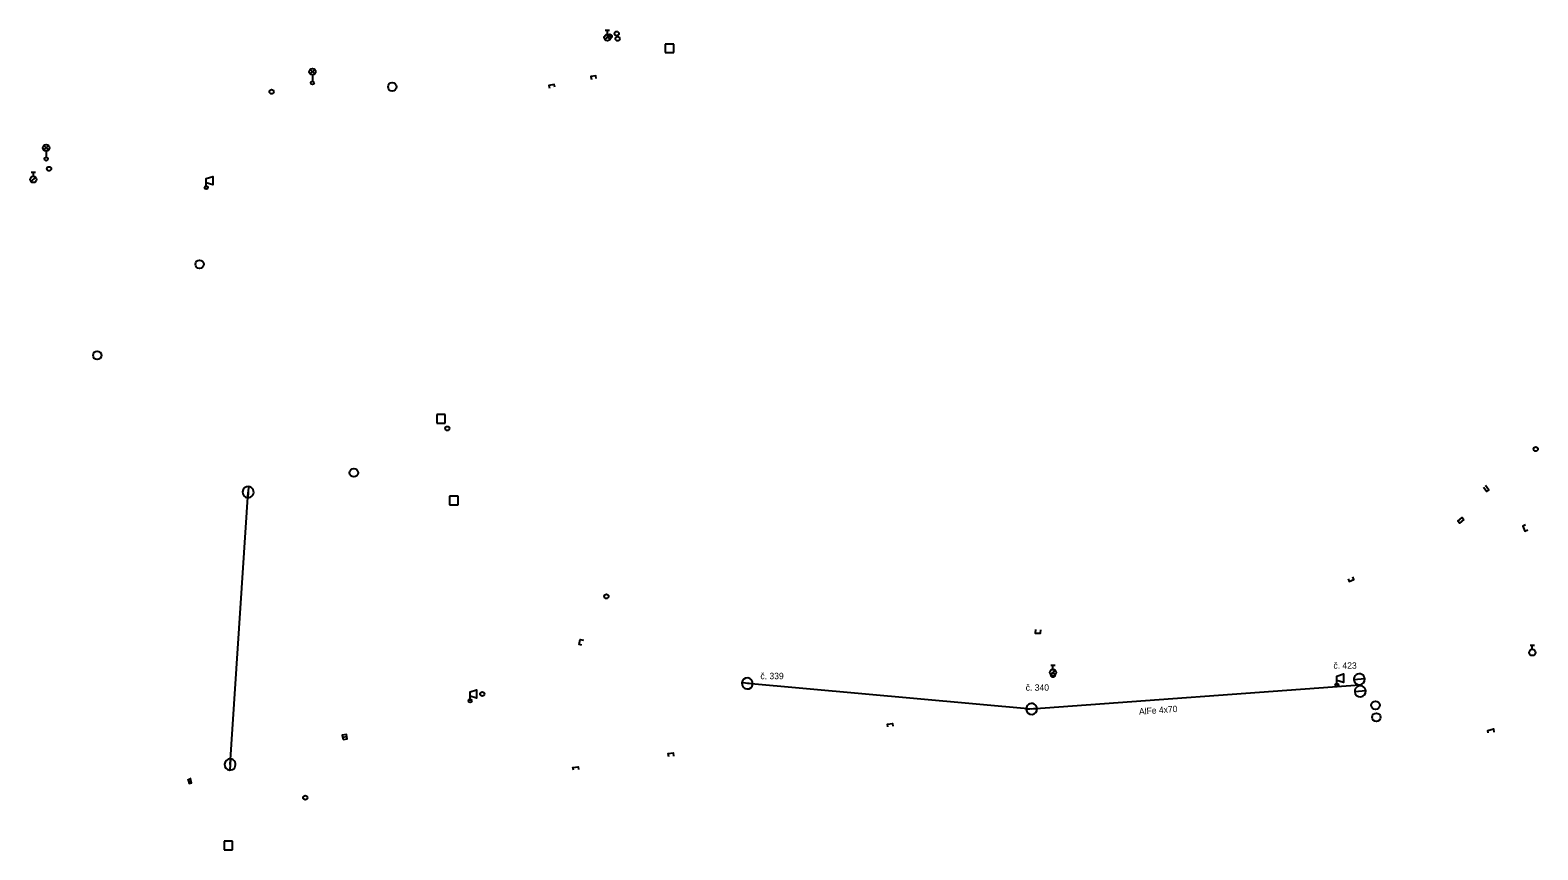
# Model space of a CAD drawing. Extents: x -577028 to -568584, y -1207664 to -1202947.
# Drawn here: x -575239.9 to -575063.1, y -1204378.5 to -1204282.4 of the extents above; entities that cross this region are included whole.
import ezdxf

# ---------------------------------------------------------------- set-up
doc = ezdxf.new("R2010")
doc.units = 0
for name, color, linetype in [('CIZÍ_NADZEM', 7, 'Continuous'), ('ELE_EON', 7, 'Continuous'), ('ELE_EON_POPIS', 7, 'Continuous')]:
    doc.layers.add(name, color=color, linetype=linetype)

msp = doc.modelspace()

# ---------------------------------------------------------------- linework, layer by layer
at = {"layer": 'CIZÍ_NADZEM'}
for p, q in [((-575172.48, -1204282.38), (-575171.98, -1204282.38)), ((-575172.23, -1204282.88), (-575172.23, -1204282.38)), ((-575172.52, -1204283.48), (-575171.93, -1204283.02)), ((-575164.44, -1204284.01), (-575165.44, -1204284.01)), ((-575165.44, -1204284.01), (-575165.44, -1204285.01)), ((-575164.44, -1204285.01), (-575164.44, -1204284.01)), ((-575165.44, -1204285.01), (-575164.44, -1204285.01)), ((-575207.08, -1204287.51), (-575206.56, -1204286.98)), ((-575206.55, -1204287.51), (-575207.08, -1204286.98)), ((-575206.82, -1204287.62), (-575206.82, -1204288.37)), ((-575238.31, -1204296.43), (-575237.79, -1204295.9)), ((-575237.78, -1204296.43), (-575238.31, -1204295.9)), ((-575238.05, -1204296.54), (-575238.05, -1204297.29)), ((-575239.84, -1204300.12), (-575239.25, -1204299.66)), ((-575239.8, -1204299.02), (-575239.3, -1204299.02)), ((-575239.55, -1204299.52), (-575239.55, -1204299.02)), ((-575191.24, -1204327.46), (-575192.24, -1204327.46)), ((-575192.24, -1204327.46), (-575192.24, -1204328.46)), ((-575192.24, -1204328.46), (-575191.24, -1204328.46)), ((-575191.24, -1204328.46), (-575191.24, -1204327.46)), ((-575189.73, -1204337.05), (-575190.73, -1204337.05)), ((-575190.73, -1204337.05), (-575190.73, -1204338.05)), ((-575189.73, -1204338.05), (-575189.73, -1204337.05)), ((-575190.73, -1204338.05), (-575189.73, -1204338.05)), ((-575064.02, -1204354.5), (-575063.52, -1204354.5)), ((-575063.77, -1204355), (-575063.77, -1204354.5)), ((-575120.27, -1204357.96), (-575119.68, -1204357.5)), ((-575120.23, -1204356.85), (-575119.73, -1204356.85)), ((-575119.98, -1204357.35), (-575119.98, -1204356.85)), ((-575203.28, -1204365.33), (-575202.78, -1204365.25)), ((-575216.19, -1204377.53), (-575217.19, -1204377.53)), ((-575217.19, -1204377.53), (-575217.19, -1204378.53)), ((-575216.19, -1204378.53), (-575216.19, -1204377.53)), ((-575217.19, -1204378.53), (-575216.19, -1204378.53))]:
    msp.add_line(p, q, dxfattribs=at)
for points in [[(-575173.53, -1204288.05), (-575173.6, -1204287.73), (-575174.18, -1204287.83), (-575174.11, -1204288.17)], [(-575178.41, -1204289.05), (-575178.48, -1204288.74), (-575179.11, -1204288.87), (-575179.04, -1204289.18)], [(-575219.27, -1204300.84), (-575219.27, -1204299.79), (-575218.52, -1204299.54), (-575218.52, -1204300.54), (-575219.27, -1204300.29)], [(-575069.49, -1204335.97), (-575069.11, -1204336.49), (-575068.86, -1204336.33), (-575069.24, -1204335.8)], [(-575071.81, -1204339.78), (-575072.29, -1204340.2), (-575072.49, -1204339.97), (-575072.01, -1204339.55), (-575071.81, -1204339.78)], [(-575064.57, -1204340.41), (-575064.89, -1204340.55), (-575064.65, -1204341.14), (-575064.31, -1204340.98)], [(-575085.38, -1204346.74), (-575085.25, -1204347.04), (-575084.69, -1204346.81), (-575084.82, -1204346.5)], [(-575122.04, -1204352.68), (-575122.06, -1204353.1), (-575121.44, -1204353.11), (-575121.42, -1204352.71)], [(-575175.24, -1204354.51), (-575175.55, -1204354.44), (-575175.42, -1204353.85), (-575175.03, -1204353.95)], [(-575086.68, -1204359.2), (-575086.68, -1204358.15), (-575085.93, -1204357.9), (-575085.93, -1204358.9), (-575086.68, -1204358.65)], [(-575188.33, -1204361.05), (-575188.33, -1204360), (-575187.58, -1204359.75), (-575187.58, -1204360.75), (-575188.33, -1204360.5)], [(-575139.34, -1204364.11), (-575139.38, -1204363.77), (-575138.8, -1204363.69), (-575138.76, -1204364.03)], [(-575068.94, -1204364.81), (-575069, -1204364.51), (-575068.32, -1204364.35), (-575068.27, -1204364.71)], [(-575165.04, -1204367.62), (-575165.1, -1204367.21), (-575164.53, -1204367.14), (-575164.47, -1204367.54)], [(-575176.22, -1204369.2), (-575176.27, -1204368.88), (-575175.67, -1204368.78), (-575175.62, -1204369.12)], [(-575221.45, -1204370.18), (-575221.29, -1204370.75), (-575221.01, -1204370.67), (-575221.17, -1204370.1)]]:
    msp.add_lwpolyline(points, dxfattribs=at)
msp.add_lwpolyline([(-575203.23, -1204365.58), (-575202.74, -1204365.49), (-575202.83, -1204365), (-575203.32, -1204365.09)], close=True, dxfattribs=at)
for centre, radius in [((-575172.23, -1204283.25), 0.375), ((-575171.96, -1204283.1), 0.25), ((-575171.14, -1204282.78), 0.25), ((-575171.04, -1204283.39), 0.25), ((-575206.82, -1204287.25), 0.375), ((-575211.61, -1204289.6), 0.25), ((-575206.82, -1204288.57), 0.2), ((-575197.46, -1204289.03), 0.5), ((-575238.05, -1204296.17), 0.375), ((-575238.05, -1204297.49), 0.2), ((-575237.71, -1204298.64), 0.25), ((-575239.55, -1204299.89), 0.375), ((-575219.27, -1204300.84), 0.2), ((-575220.05, -1204309.84), 0.5), ((-575232.05, -1204320.52), 0.5), ((-575191, -1204329.1), 0.25), ((-575063.37, -1204331.52), 0.25), ((-575201.96, -1204334.29), 0.5), ((-575172.35, -1204348.8), 0.25), ((-575063.77, -1204355.37), 0.375), ((-575119.98, -1204357.73), 0.375), ((-575119.98, -1204358.03), 0.25), ((-575186.91, -1204360.25), 0.25), ((-575086.68, -1204359.2), 0.2), ((-575188.33, -1204361.05), 0.2), ((-575082.15, -1204361.57), 0.5), ((-575082.06, -1204362.98), 0.5), ((-575207.66, -1204372.41), 0.25)]:
    msp.add_circle(centre, radius, dxfattribs=at)
at = {"layer": 'ELE_EON'}
for p, q in [((-575214.32, -1204335.92), (-575214.4, -1204337.22)), ((-575083.4, -1204358.48), (-575084.7, -1204358.58)), ((-575155.17, -1204359.07), (-575156.47, -1204358.95)), ((-575083.3, -1204359.88), (-575084.6, -1204359.98)), ((-575121.83, -1204361.96), (-575123.13, -1204362.06)), ((-575216.44, -1204367.87), (-575216.52, -1204369.17))]:
    msp.add_line(p, q, dxfattribs=at)
for points in [[(-575216.48, -1204368.52), (-575214.36, -1204336.57)], [(-575084, -1204359.23), (-575122.48, -1204362.01), (-575155.82, -1204359.01)]]:
    msp.add_lwpolyline(points, dxfattribs=at)
for centre, start, end in [((-575214.36, -1204336.57), 86.2, 266.2), ((-575214.36, -1204336.57), 266.2, 86.2), ((-575155.82, -1204359.01), 354.8583, 174.8583), ((-575084.05, -1204358.53), 4.1322, 184.1322), ((-575084.05, -1204358.53), 184.1322, 4.1322), ((-575155.82, -1204359.01), 174.8583, 354.8583), ((-575083.95, -1204359.93), 4.1322, 184.1322), ((-575083.95, -1204359.93), 184.1322, 4.1322), ((-575122.48, -1204362.01), 4.1322, 184.1322), ((-575122.48, -1204362.01), 184.1322, 4.1322), ((-575216.48, -1204368.52), 86.2, 266.2), ((-575216.48, -1204368.52), 266.2, 86.2)]:
    msp.add_arc(centre, 0.65, start, end, dxfattribs=at)

# ---------------------------------------------------------------- texts
at = {"layer": 'ELE_EON_POPIS'}
for s, p in [('č. 423', (-575087.09, -1204357.28)), ('č. 339', (-575154.29, -1204358.51)), ('č. 340', (-575123.18, -1204359.87))]:
    msp.add_text(s, height=0.75, dxfattribs=at).set_placement(p)
msp.add_text('AlFe 4x70', height=0.75, rotation=4.1322, dxfattribs=at).set_placement((-575109.87, -1204362.68))

doc.saveas('drawing.dxf')
